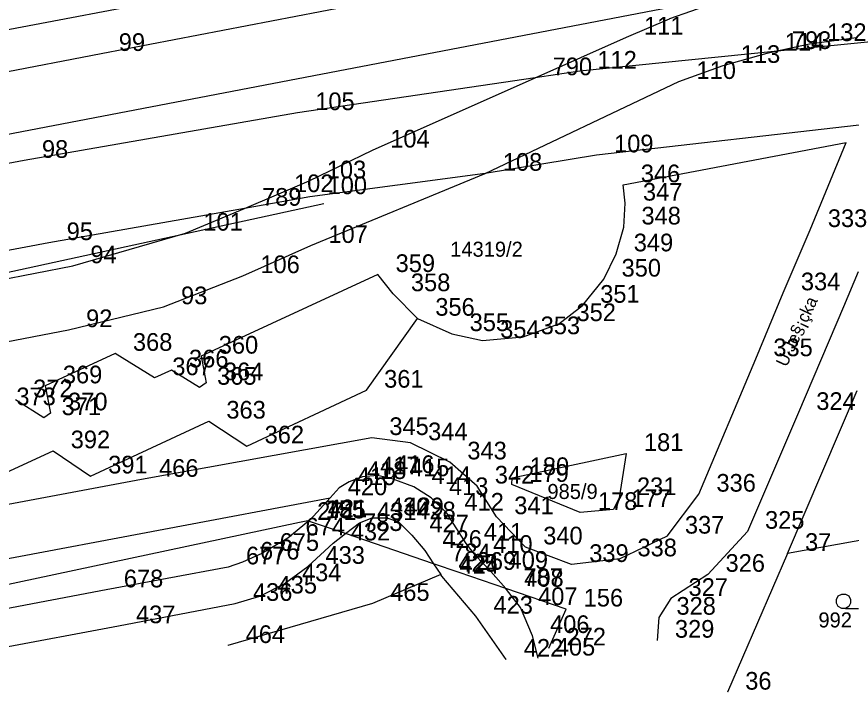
# Model space of a CAD drawing. Extents: x -822293 to -820259, y -1071573 to -1068794.
# Drawn here: x -822026.3 to -821931.9, y -1070471 to -1070394.6 of the extents above; entities that cross this region are included whole.
import ezdxf

# ---------------------------------------------------------------- set-up
doc = ezdxf.new("R2010")
doc.units = 0
for name, color, linetype in [('Vrstva 1', 7, 'Continuous'), ('Vrstva 10', 7, 'Continuous'), ('Vrstva 15', 7, 'Continuous'), ('Vrstva 2', 7, 'Continuous'), ('Vrstva 3', 7, 'Continuous'), ('Vrstva 5', 7, 'Continuous'), ('Vrstva 8', 7, 'Continuous'), ('Vrstva 9', 7, 'Continuous')]:
    doc.layers.add(name, color=color, linetype=linetype)

# ---------------------------------------------------------------- blocks, each defined once
blk = doc.blocks.new('Z304')
at = {"layer": 'Vrstva 2'}
for p, q in [((-80, 20), (-60, 60)), ((-80, -20), (-80, 20)), ((-60, 60), (-20, 80)), ((-20, 80), (20, 80)), ((20, 80), (60, 60)), ((60, 60), (80, 20)), ((80, 20), (80, -20)), ((-60, -60), (-80, -20)), ((-20, -80), (-60, -60)), ((20, -80), (-20, -80)), ((60, -60), (20, -80)), ((20, -80), (170, -80)), ((80, -20), (60, -60))]:
    blk.add_line(p, q, dxfattribs=at)

msp = doc.modelspace()

# ---------------------------------------------------------------- linework, layer by layer
at = {"layer": 'Vrstva 1'}
msp.add_line((-822089.22, -1070436.96), (-821991.55, -1070415.71), dxfattribs=at)
at = {"layer": 'Vrstva 2'}
for p, q in [((-821939.09, -1070455.33), (-821931.19, -1070436.89)), ((-821970.26, -1070446.75), (-821957.33, -1070444.03)), ((-821957.33, -1070444.03), (-821958.12, -1070449.02)), ((-821970.3, -1070447.52), (-821970.26, -1070446.75)), ((-821962.54, -1070450.7), (-821970.3, -1070447.52)), ((-821958.12, -1070449.02), (-821958.76, -1070450.36)), ((-821958.76, -1070450.36), (-821962.54, -1070450.7)), ((-821993.37, -1070451.63), (-821994.32, -1070451.83)), ((-821993.29, -1070451.66), (-821993.37, -1070451.63)), ((-821989.13, -1070453.08), (-821993.29, -1070451.66)), ((-821994.32, -1070451.83), (-822044.44, -1070462.46)), ((-821923.25, -1070452.47), (-821939.09, -1070455.33)), ((-821979.14, -1070456.5), (-821989.13, -1070453.08)), ((-821939.09, -1070455.33), (-821945.86, -1070471.04)), ((-821976.26, -1070457.48), (-821979.14, -1070456.5)), ((-821978.34, -1070457.69), (-821986.06, -1070460.99)), ((-821978.2, -1070457.9), (-821978.34, -1070457.69)), ((-821974.36, -1070462.44), (-821978.2, -1070457.9)), ((-821970.96, -1070459.3), (-821976.26, -1070457.48)), ((-821964.15, -1070461.63), (-821970.96, -1070459.3)), ((-821986.06, -1070460.99), (-822002.42, -1070465.76)), ((-821966.09, -1070466.04), (-821964.15, -1070461.63)), ((-821970.93, -1070467.31), (-821974.36, -1070462.44))]:
    msp.add_line(p, q, dxfattribs=at)
at = {"layer": 'Vrstva 3'}
for p, q in [((-822016.78, -1070398.75), (-821946.15, -1070385.15)), ((-821983.7, -1070387.69), (-822075.3, -1070405.26)), ((-821947.82, -1070392.63), (-822050.78, -1070412.39)), ((-821947.69, -1070393.16), (-821952.44, -1070394.83)), ((-821957.32, -1070396.89), (-821952.44, -1070394.83)), ((-821967.66, -1070401.5), (-821957.32, -1070396.89)), ((-821922.05, -1070396.66), (-821940.58, -1070398.53)), ((-821936.59, -1070397.63), (-821931.31, -1070396.91)), ((-821940.58, -1070398.53), (-821936.59, -1070397.63)), ((-822092.17, -1070413.23), (-822016.78, -1070398.75)), ((-821940.58, -1070398.53), (-821962.6, -1070400.75)), ((-821946.36, -1070400.1), (-821941.39, -1070398.71)), ((-821941.39, -1070398.71), (-821940.58, -1070398.53)), ((-821951.38, -1070401.92), (-821946.36, -1070400.1)), ((-821967.66, -1070401.5), (-821994.54, -1070405.45)), ((-821986.05, -1070409.68), (-821967.66, -1070401.5)), ((-821962.6, -1070400.75), (-821967.66, -1070401.5)), ((-821973.3, -1070412.31), (-821951.38, -1070401.92)), ((-821994.54, -1070405.45), (-822025.48, -1070410.85)), ((-821928.02, -1070406.53), (-821960.71, -1070410.23)), ((-821957.68, -1070413.61), (-821932.45, -1070408.83)), ((-821936.51, -1070418.68), (-821932.45, -1070408.83)), ((-821993.23, -1070413.17), (-821986.05, -1070409.68)), ((-822025.48, -1070410.85), (-822054.22, -1070416.3)), ((-821960.71, -1070410.23), (-821973.3, -1070412.31)), ((-821973.3, -1070412.31), (-821993.14, -1070414.96)), ((-821993.05, -1070420.48), (-821973.3, -1070412.31)), ((-821996.94, -1070414.73), (-821993.23, -1070413.17)), ((-821957.44, -1070415.69), (-821957.68, -1070413.61)), ((-822000.56, -1070416.27), (-821996.94, -1070414.73)), ((-821993.14, -1070414.96), (-822000.56, -1070416.27)), ((-821957.61, -1070418.39), (-821957.44, -1070415.69)), ((-822000.56, -1070416.27), (-822022.68, -1070420.16)), ((-822007.21, -1070419.09), (-822000.56, -1070416.27)), ((-821958.48, -1070421.43), (-821957.61, -1070418.39)), ((-822019.99, -1070422.78), (-822007.21, -1070419.09)), ((-821939.56, -1070425.84), (-821936.51, -1070418.68)), ((-822022.68, -1070420.16), (-822052.18, -1070425.71)), ((-822000.75, -1070423.9), (-821993.05, -1070420.48)), ((-821959.86, -1070424.29), (-821958.48, -1070421.43)), ((-822050.5, -1070428.65), (-822019.99, -1070422.78)), ((-822009.73, -1070427.42), (-822000.75, -1070423.9)), ((-821985.44, -1070423.77), (-822005.46, -1070433.01)), ((-821983.71, -1070425.94), (-821985.44, -1070423.77)), ((-821962.28, -1070427.25), (-821959.86, -1070424.29)), ((-821931.07, -1070423.46), (-821932.74, -1070427.42)), ((-821980.95, -1070428.72), (-821983.71, -1070425.94)), ((-821942.68, -1070433.3), (-821939.56, -1070425.84)), ((-822020.48, -1070430.01), (-822009.73, -1070427.42)), ((-821964.96, -1070429.33), (-821962.28, -1070427.25)), ((-821932.74, -1070427.42), (-821937.82, -1070439.38)), ((-821986.74, -1070436.86), (-821980.95, -1070428.72)), ((-821980.95, -1070428.72), (-821977.06, -1070430.46)), ((-821969.02, -1070430.81), (-821964.96, -1070429.33)), ((-822049.47, -1070435.55), (-822020.48, -1070430.01)), ((-821977.06, -1070430.46), (-821973.6, -1070431.24)), ((-821973.6, -1070431.24), (-821969.02, -1070430.81)), ((-822015.18, -1070432.69), (-822023.11, -1070436.37)), ((-822010.72, -1070435.45), (-822015.18, -1070432.69)), ((-822005.46, -1070433.01), (-822004.88, -1070436.02)), ((-821949.12, -1070448.63), (-821942.68, -1070433.3)), ((-822008.83, -1070434.57), (-822010.72, -1070435.45)), ((-822005.65, -1070436.53), (-822008.83, -1070434.57)), ((-822023.11, -1070436.37), (-822022.52, -1070439.43)), ((-822004.88, -1070436.02), (-822005.65, -1070436.53)), ((-822000.27, -1070443.17), (-821986.74, -1070436.86)), ((-822023.25, -1070439.97), (-822026.47, -1070437.95)), ((-822022.52, -1070439.43), (-822023.25, -1070439.97)), ((-821937.82, -1070439.38), (-821943.62, -1070452.83)), ((-822017.98, -1070446.57), (-822004.6, -1070440.36)), ((-822004.6, -1070440.36), (-822000.27, -1070443.17)), ((-821986.15, -1070442.22), (-822012.22, -1070446.95)), ((-821981.76, -1070442.81), (-821986.15, -1070442.22)), ((-821977.32, -1070444.98), (-821981.76, -1070442.81)), ((-822035.65, -1070449.92), (-822022.22, -1070443.72)), ((-822022.22, -1070443.72), (-822017.98, -1070446.57)), ((-821974.21, -1070447.71), (-821977.32, -1070444.98)), ((-822012.22, -1070446.95), (-822059.18, -1070455.81)), ((-821987.18, -1070446.67), (-821988.69, -1070447.2)), ((-821985.5, -1070446.52), (-821987.18, -1070446.67)), ((-821983.82, -1070446.88), (-821985.5, -1070446.52)), ((-821981.37, -1070447.78), (-821983.82, -1070446.88)), ((-821989.83, -1070447.89), (-821990.86, -1070449.03)), ((-821988.69, -1070447.2), (-821989.83, -1070447.89)), ((-821979.4, -1070449.02), (-821981.37, -1070447.78)), ((-821972.01, -1070451.18), (-821974.21, -1070447.71)), ((-821952.69, -1070453.38), (-821949.12, -1070448.63)), ((-822060.29, -1070462.11), (-821990.86, -1070449.03)), ((-821990.86, -1070449.03), (-821993.13, -1070451.53)), ((-821977.65, -1070450.78), (-821979.4, -1070449.02)), ((-821975.46, -1070454.18), (-821977.65, -1070450.78)), ((-821993.29, -1070451.66), (-821995.64, -1070453.59)), ((-821993.13, -1070451.53), (-821993.29, -1070451.66)), ((-821987.54, -1070451.85), (-821986.08, -1070451.31)), ((-821986.08, -1070451.31), (-821984.44, -1070451.31)), ((-821984.44, -1070451.31), (-821983.1, -1070451.76)), ((-821968.73, -1070454.6), (-821972.01, -1070451.18)), ((-821989.13, -1070453.08), (-821987.54, -1070451.85)), ((-821983.1, -1070451.76), (-821981.61, -1070453.24)), ((-821995.64, -1070453.59), (-821998.57, -1070455.33)), ((-821990.52, -1070454.15), (-821989.13, -1070453.08)), ((-821981.61, -1070453.24), (-821980.14, -1070454.99)), ((-821952.69, -1070453.38), (-821958.06, -1070455.95)), ((-821943.62, -1070452.83), (-821948.09, -1070457.7)), ((-821993.38, -1070456.8), (-821990.52, -1070454.15)), ((-821974.4, -1070455.56), (-821975.46, -1070454.18)), ((-821998.57, -1070455.33), (-822000.79, -1070456.32)), ((-821980.14, -1070454.99), (-821979.14, -1070456.5)), ((-821963.52, -1070456.59), (-821968.73, -1070454.6)), ((-822000.79, -1070456.32), (-822002.38, -1070456.86)), ((-821972.65, -1070457.36), (-821974.4, -1070455.56)), ((-821958.06, -1070455.95), (-821963.52, -1070456.59)), ((-822002.38, -1070456.86), (-822016.21, -1070459.46)), ((-821996.04, -1070458.77), (-821993.38, -1070456.8)), ((-821979.14, -1070456.5), (-821978.34, -1070457.69)), ((-821970.96, -1070459.3), (-821972.65, -1070457.36)), ((-821948.09, -1070457.7), (-821952.28, -1070460.43)), ((-821998.8, -1070460.16), (-821996.04, -1070458.77)), ((-822016.21, -1070459.46), (-822040.69, -1070464.07)), ((-822001.59, -1070460.99), (-821998.8, -1070460.16)), ((-821970.88, -1070459.39), (-821970.96, -1070459.3)), ((-821969.31, -1070461.46), (-821970.88, -1070459.39)), ((-822014.83, -1070463.52), (-822001.59, -1070460.99)), ((-821952.28, -1070460.43), (-821953.65, -1070462.56)), ((-821967.96, -1070464.63), (-821969.31, -1070461.46)), ((-821953.65, -1070462.56), (-821953.82, -1070465.16)), ((-822040.52, -1070468.35), (-822014.83, -1070463.52)), ((-821967.31, -1070467.18), (-821967.96, -1070464.63))]:
    msp.add_line(p, q, dxfattribs=at)
at = {"layer": 'Vrstva 8'}
for p, q in [((-821952.44, -1070394.83), (-821952.44, -1070394.83)), ((-821957.32, -1070396.89), (-821957.32, -1070396.89)), ((-821936.59, -1070397.63), (-821936.59, -1070397.63)), ((-822016.78, -1070398.75), (-822016.78, -1070398.75)), ((-821941.39, -1070398.71), (-821941.39, -1070398.71)), ((-821940.58, -1070398.53), (-821940.58, -1070398.53)), ((-821946.36, -1070400.1), (-821946.36, -1070400.1)), ((-821967.66, -1070401.5), (-821967.66, -1070401.5)), ((-821962.6, -1070400.75), (-821962.6, -1070400.75)), ((-821951.38, -1070401.92), (-821951.38, -1070401.92)), ((-821994.54, -1070405.45), (-821994.54, -1070405.45)), ((-821932.45, -1070408.83), (-821932.45, -1070408.83)), ((-821986.05, -1070409.68), (-821986.05, -1070409.68)), ((-822025.48, -1070410.85), (-822025.48, -1070410.85)), ((-821960.71, -1070410.23), (-821960.71, -1070410.23)), ((-821973.3, -1070412.31), (-821973.3, -1070412.31)), ((-821993.23, -1070413.17), (-821993.23, -1070413.17)), ((-821957.68, -1070413.61), (-821957.68, -1070413.61)), ((-821996.94, -1070414.73), (-821996.94, -1070414.73)), ((-821993.14, -1070414.96), (-821993.14, -1070414.96)), ((-821957.44, -1070415.69), (-821957.44, -1070415.69)), ((-822000.56, -1070416.27), (-822000.56, -1070416.27)), ((-821957.61, -1070418.39), (-821957.61, -1070418.39)), ((-822007.21, -1070419.09), (-822007.21, -1070419.09)), ((-821936.51, -1070418.68), (-821936.51, -1070418.68)), ((-822022.68, -1070420.16), (-822022.68, -1070420.16)), ((-821993.05, -1070420.48), (-821993.05, -1070420.48)), ((-821958.48, -1070421.43), (-821958.48, -1070421.43)), ((-822019.99, -1070422.78), (-822019.99, -1070422.78)), ((-822000.75, -1070423.9), (-822000.75, -1070423.9)), ((-821985.44, -1070423.77), (-821985.44, -1070423.77)), ((-821959.86, -1070424.29), (-821959.86, -1070424.29)), ((-821983.71, -1070425.94), (-821983.71, -1070425.94)), ((-821939.56, -1070425.84), (-821939.56, -1070425.84)), ((-822009.73, -1070427.42), (-822009.73, -1070427.42)), ((-821962.28, -1070427.25), (-821962.28, -1070427.25)), ((-821932.74, -1070427.42), (-821932.74, -1070427.42)), ((-821980.95, -1070428.72), (-821980.95, -1070428.72)), ((-821964.96, -1070429.33), (-821964.96, -1070429.33)), ((-822020.48, -1070430.01), (-822020.48, -1070430.01)), ((-821977.06, -1070430.46), (-821977.06, -1070430.46)), ((-821969.02, -1070430.81), (-821969.02, -1070430.81)), ((-821973.6, -1070431.24), (-821973.6, -1070431.24)), ((-822015.18, -1070432.69), (-822015.18, -1070432.69)), ((-822005.46, -1070433.01), (-822005.46, -1070433.01)), ((-821942.68, -1070433.3), (-821942.68, -1070433.3)), ((-822008.83, -1070434.57), (-822008.83, -1070434.57)), ((-822010.72, -1070435.45), (-822010.72, -1070435.45)), ((-822023.11, -1070436.37), (-822023.11, -1070436.37)), ((-822005.65, -1070436.53), (-822005.65, -1070436.53)), ((-822004.88, -1070436.02), (-822004.88, -1070436.02)), ((-821986.74, -1070436.86), (-821986.74, -1070436.86)), ((-822022.52, -1070439.43), (-822022.52, -1070439.43)), ((-821937.82, -1070439.38), (-821937.82, -1070439.38)), ((-822023.25, -1070439.97), (-822023.25, -1070439.97)), ((-822004.6, -1070440.36), (-822004.6, -1070440.36)), ((-821986.15, -1070442.22), (-821986.15, -1070442.22)), ((-822000.27, -1070443.17), (-822000.27, -1070443.17)), ((-821981.76, -1070442.81), (-821981.76, -1070442.81)), ((-822022.22, -1070443.72), (-822022.22, -1070443.72)), ((-821957.33, -1070444.03), (-821957.33, -1070444.03)), ((-821977.32, -1070444.98), (-821977.32, -1070444.98)), ((-822017.98, -1070446.57), (-822017.98, -1070446.57)), ((-822012.22, -1070446.95), (-822012.22, -1070446.95)), ((-821987.18, -1070446.67), (-821987.18, -1070446.67)), ((-821985.5, -1070446.52), (-821985.5, -1070446.52)), ((-821983.82, -1070446.88), (-821983.82, -1070446.88)), ((-821970.26, -1070446.75), (-821970.26, -1070446.75)), ((-821989.83, -1070447.89), (-821989.83, -1070447.89)), ((-821988.69, -1070447.2), (-821988.69, -1070447.2)), ((-821981.37, -1070447.78), (-821981.37, -1070447.78)), ((-821974.21, -1070447.71), (-821974.21, -1070447.71)), ((-821970.3, -1070447.52), (-821970.3, -1070447.52)), ((-821949.12, -1070448.63), (-821949.12, -1070448.63)), ((-821990.86, -1070449.03), (-821990.86, -1070449.03)), ((-821979.4, -1070449.02), (-821979.4, -1070449.02)), ((-821958.12, -1070449.02), (-821958.12, -1070449.02)), ((-821977.65, -1070450.78), (-821977.65, -1070450.78)), ((-821962.54, -1070450.7), (-821962.54, -1070450.7)), ((-821958.76, -1070450.36), (-821958.76, -1070450.36)), ((-821993.37, -1070451.63), (-821993.37, -1070451.63)), ((-821993.29, -1070451.66), (-821993.29, -1070451.66)), ((-821993.13, -1070451.53), (-821993.13, -1070451.53)), ((-821986.08, -1070451.31), (-821986.08, -1070451.31)), ((-821984.44, -1070451.31), (-821984.44, -1070451.31)), ((-821972.01, -1070451.18), (-821972.01, -1070451.18)), ((-821994.32, -1070451.83), (-821994.32, -1070451.83)), ((-821987.54, -1070451.85), (-821987.54, -1070451.85)), ((-821983.1, -1070451.76), (-821983.1, -1070451.76)), ((-821995.64, -1070453.59), (-821995.64, -1070453.59)), ((-821989.13, -1070453.08), (-821989.13, -1070453.08)), ((-821981.61, -1070453.24), (-821981.61, -1070453.24)), ((-821952.69, -1070453.38), (-821952.69, -1070453.38)), ((-821943.62, -1070452.83), (-821943.62, -1070452.83)), ((-821990.52, -1070454.15), (-821990.52, -1070454.15)), ((-821975.46, -1070454.18), (-821975.46, -1070454.18)), ((-821998.57, -1070455.33), (-821998.57, -1070455.33)), ((-821980.14, -1070454.99), (-821980.14, -1070454.99)), ((-821968.73, -1070454.6), (-821968.73, -1070454.6)), ((-821939.09, -1070455.33), (-821939.09, -1070455.33)), ((-822000.79, -1070456.32), (-822000.79, -1070456.32)), ((-821974.4, -1070455.56), (-821974.4, -1070455.56)), ((-821958.06, -1070455.95), (-821958.06, -1070455.95)), ((-822002.38, -1070456.86), (-822002.38, -1070456.86)), ((-821993.38, -1070456.8), (-821993.38, -1070456.8)), ((-821979.14, -1070456.5), (-821979.14, -1070456.5)), ((-821972.65, -1070457.36), (-821972.65, -1070457.36)), ((-821963.52, -1070456.59), (-821963.52, -1070456.59)), ((-821978.34, -1070457.69), (-821978.34, -1070457.69)), ((-821978.2, -1070457.9), (-821978.2, -1070457.9)), ((-821976.26, -1070457.48), (-821976.26, -1070457.48)), ((-821948.09, -1070457.7), (-821948.09, -1070457.7)), ((-821996.04, -1070458.77), (-821996.04, -1070458.77)), ((-822016.21, -1070459.46), (-822016.21, -1070459.46)), ((-821998.8, -1070460.16), (-821998.8, -1070460.16)), ((-821970.96, -1070459.3), (-821970.96, -1070459.3)), ((-821970.88, -1070459.39), (-821970.88, -1070459.39)), ((-822001.59, -1070460.99), (-822001.59, -1070460.99)), ((-821986.06, -1070460.99), (-821986.06, -1070460.99)), ((-821952.28, -1070460.43), (-821952.28, -1070460.43)), ((-821969.31, -1070461.46), (-821969.31, -1070461.46)), ((-821964.15, -1070461.63), (-821964.15, -1070461.63)), ((-821974.36, -1070462.44), (-821974.36, -1070462.44)), ((-821953.65, -1070462.56), (-821953.65, -1070462.56)), ((-822014.83, -1070463.52), (-822014.83, -1070463.52)), ((-821967.96, -1070464.63), (-821967.96, -1070464.63)), ((-822002.42, -1070465.76), (-822002.42, -1070465.76)), ((-821953.82, -1070465.16), (-821953.82, -1070465.16)), ((-821966.09, -1070466.04), (-821966.09, -1070466.04)), ((-821970.93, -1070467.31), (-821970.93, -1070467.31)), ((-821967.31, -1070467.18), (-821967.31, -1070467.18)), ((-821945.86, -1070471.04), (-821945.86, -1070471.04))]:
    msp.add_line(p, q, dxfattribs=at)

# ---------------------------------------------------------------- block references
at = {"layer": 'Vrstva 10', "xscale": 0.01, "yscale": 0.01}
msp.add_blockref('Z304', (-821932.73, -1070460.74), dxfattribs=at)

# ---------------------------------------------------------------- texts
at = {"layer": 'Vrstva 15'}
msp.add_text('U Je§¡çka', height=1.399, rotation=65, dxfattribs=at).set_placement((-821939.182, -1070434.305))
at = {"layer": 'Vrstva 5'}
for s, p in [('14319/2', (-821977.26, -1070421.74)), ('985/9', (-821966.256, -1070449.16)), ('992', (-821935.576, -1070463.7))]:
    msp.add_text(s, height=1.7, dxfattribs=at).set_placement(p)
at = {"layer": 'Vrstva 9'}
for s, p in [('111', (-821955.32, -1070396.59)), ('132', (-821934.59, -1070397.33)), ('99', (-822014.78, -1070398.45)), ('114', (-821939.39, -1070398.41)), ('793', (-821938.58, -1070398.23)), ('113', (-821944.36, -1070399.8)), ('112', (-821960.6, -1070400.45)), ('790', (-821965.66, -1070401.2)), ('110', (-821949.38, -1070401.62)), ('105', (-821992.54, -1070405.15)), ('104', (-821984.05, -1070409.38)), ('109', (-821958.71, -1070409.93)), ('98', (-822023.48, -1070410.55)), ('108', (-821971.3, -1070412.01)), ('103', (-821991.23, -1070412.87)), ('346', (-821955.68, -1070413.31)), ('102', (-821994.94, -1070414.43)), ('100', (-821991.14, -1070414.66)), ('789', (-821998.56, -1070415.97)), ('347', (-821955.44, -1070415.39)), ('101', (-822005.21, -1070418.79)), ('348', (-821955.61, -1070418.09)), ('333', (-821934.51, -1070418.38)), ('95', (-822020.68, -1070419.86)), ('107', (-821991.05, -1070420.18)), ('349', (-821956.48, -1070421.13)), ('94', (-822017.99, -1070422.48)), ('359', (-821983.44, -1070423.47)), ('106', (-821998.75, -1070423.6)), ('350', (-821957.86, -1070423.99)), ('358', (-821981.71, -1070425.64)), ('334', (-821937.56, -1070425.54)), ('93', (-822007.73, -1070427.12)), ('351', (-821960.28, -1070426.95)), ('356', (-821978.95, -1070428.42)), ('352', (-821962.96, -1070429.03)), ('92', (-822018.48, -1070429.71)), ('355', (-821975.06, -1070430.16)), ('354', (-821971.6, -1070430.94)), ('353', (-821967.02, -1070430.51)), ('368', (-822013.18, -1070432.39)), ('360', (-822003.46, -1070432.71)), ('335', (-821940.68, -1070433)), ('366', (-822006.83, -1070434.27)), ('367', (-822008.72, -1070435.15)), ('364', (-822002.88, -1070435.72)), ('369', (-822021.11, -1070436.07)), ('365', (-822003.65, -1070436.23)), ('361', (-821984.74, -1070436.56)), ('372', (-822024.47, -1070437.65)), ('373', (-822026.37, -1070438.55)), ('370', (-822020.52, -1070439.13)), ('324', (-821935.82, -1070439.08)), ('371', (-822021.25, -1070439.67)), ('363', (-822002.6, -1070440.06)), ('345', (-821984.15, -1070441.92)), ('362', (-821998.27, -1070442.87)), ('344', (-821979.76, -1070442.51)), ('392', (-822020.22, -1070443.42)), ('181', (-821955.33, -1070443.73)), ('343', (-821975.32, -1070444.68)), ('391', (-822015.98, -1070446.27)), ('466', (-822010.22, -1070446.65)), ('418', (-821986.69, -1070446.9)), ('417', (-821985.18, -1070446.37)), ('416', (-821983.5, -1070446.22)), ('415', (-821981.82, -1070446.58)), ('180', (-821968.26, -1070446.45)), ('419', (-821987.83, -1070447.59)), ('414', (-821979.37, -1070447.48)), ('342', (-821972.21, -1070447.41)), ('179', (-821968.3, -1070447.22)), ('420', (-821988.86, -1070448.73)), ('413', (-821977.4, -1070448.72)), ('231', (-821956.12, -1070448.72)), ('336', (-821947.12, -1070448.33)), ('412', (-821975.65, -1070450.48)), ('341', (-821970.01, -1070450.88)), ('178', (-821960.54, -1070450.4)), ('177', (-821956.76, -1070450.06)), ('271', (-821992.32, -1070451.53)), ('155', (-821991.37, -1070451.33)), ('785', (-821991.29, -1070451.36)), ('421', (-821991.13, -1070451.23)), ('431', (-821985.54, -1070451.55)), ('430', (-821984.08, -1070451.01)), ('429', (-821982.44, -1070451.01)), ('428', (-821981.1, -1070451.46)), ('783', (-821987.13, -1070452.78)), ('325', (-821941.62, -1070452.53)), ('674', (-821993.64, -1070453.29)), ('427', (-821979.61, -1070452.94)), ('337', (-821950.69, -1070453.08)), ('432', (-821988.52, -1070453.85)), ('426', (-821978.14, -1070454.69)), ('411', (-821973.46, -1070453.88)), ('340', (-821966.73, -1070454.3)), ('675', (-821996.57, -1070455.03)), ('410', (-821972.4, -1070455.26)), ('338', (-821956.06, -1070455.65)), ('37', (-821937.09, -1070455.03)), ('677', (-822000.38, -1070456.56)), ('676', (-821998.79, -1070456.02)), ('433', (-821991.38, -1070456.5)), ('784', (-821977.14, -1070456.2)), ('339', (-821961.52, -1070456.29)), ('425', (-821976.34, -1070457.39)), ('269', (-821974.26, -1070457.18)), ('409', (-821970.65, -1070457.06)), ('326', (-821946.09, -1070457.4)), ('434', (-821994.04, -1070458.47)), ('424', (-821976.2, -1070457.6)), ('678', (-822014.21, -1070459.16)), ('787', (-821968.96, -1070459)), ('408', (-821968.88, -1070459.09)), ('435', (-821996.8, -1070459.86)), ('327', (-821950.28, -1070460.13)), ('436', (-821999.59, -1070460.69)), ('465', (-821984.06, -1070460.69)), ('407', (-821967.31, -1070461.16)), ('423', (-821972.36, -1070462.14)), ('156', (-821962.15, -1070461.33)), ('328', (-821951.65, -1070462.26)), ('437', (-822012.83, -1070463.22)), ('406', (-821965.96, -1070464.33)), ('329', (-821951.82, -1070464.86)), ('464', (-822000.42, -1070465.46)), ('272', (-821964.09, -1070465.74)), ('405', (-821965.31, -1070466.88)), ('422', (-821968.93, -1070467.01)), ('36', (-821943.86, -1070470.74))]:
    msp.add_text(s, height=2, dxfattribs=at).set_placement(p)

doc.saveas('drawing.dxf')
